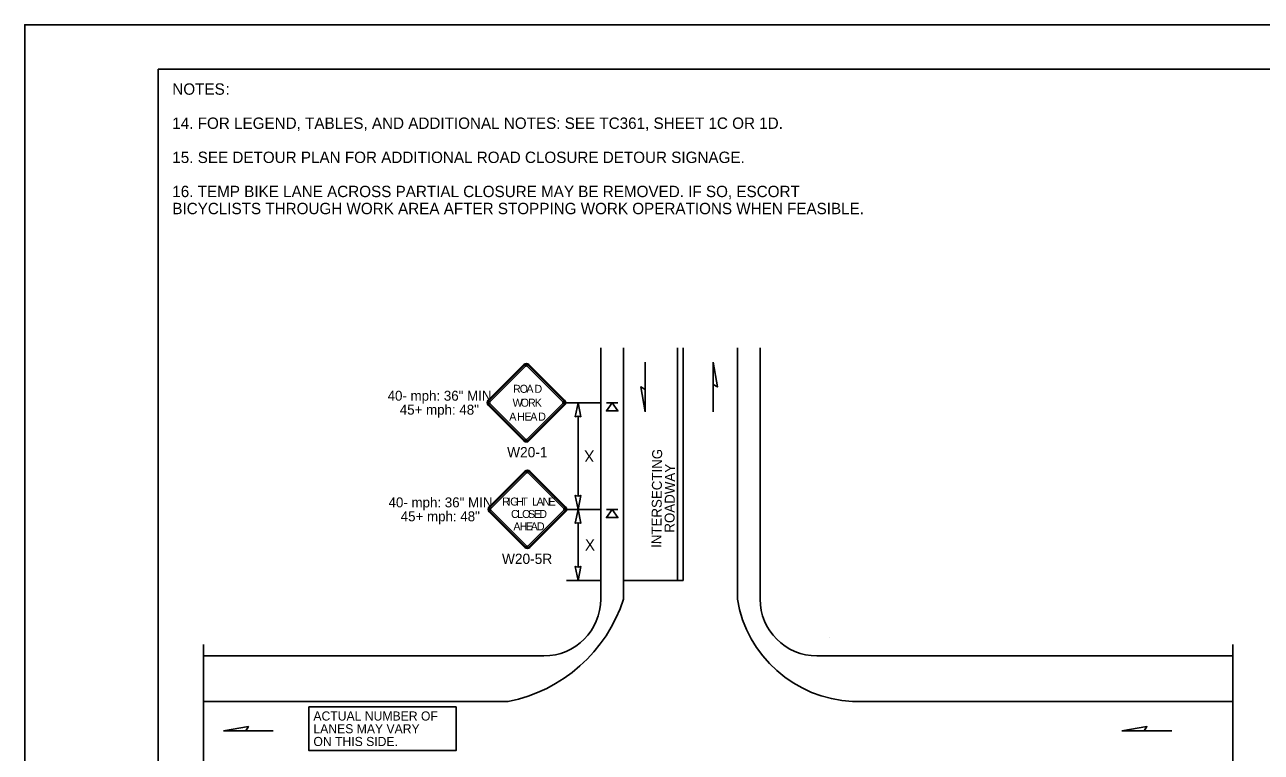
# Model space of a CAD drawing. Extents: x 99958 to 100176, y 99935 to 100011.
# Drawn here: x 100039.06 to 100047.76, y 99975.57 to 99980.69 of the extents above; entities that cross this region are included whole.
import ezdxf

# ---------------------------------------------------------------- set-up
doc = ezdxf.new("R2010")
doc.units = 0
for name, color, linetype in [('RD_ED_ShoulderPavedEdge', 7, 'Continuous'), ('RD_MK_LineDblYellowCenter', 7, 'Continuous'), ('RD_MK_LineEdgeWhite', 7, 'Continuous'), ('RD_MK_LineStop', 7, 'Continuous'), ('SH_DE_DetailBody1Text', 7, 'Continuous'), ('SH_GI_GeneralNotesBodyText', 7, 'Continuous'), ('SH_GI_PlotLimits', 7, 'Continuous'), ('SH_GI_SheetBorder', 7, 'Continuous'), ('SH_TI_Tables', 7, 'Continuous'), ('TR_SN_ConstructionSigns', 7, 'Continuous'), ('TR_WZ_PortableSignMountBlk-Org', 7, 'Continuous'), ('TR_WZ_WorkZoneDetails', 7, 'Continuous'), ('TR_WZ_WorkZoneTextCurrent', 7, 'Continuous')]:
    doc.layers.add(name, color=color, linetype=linetype)

msp = doc.modelspace()

# ---------------------------------------------------------------- linework, layer by layer
at = {"layer": 'RD_ED_ShoulderPavedEdge'}
for p, q in [((100042.7119, 99976.2485), (100040.32, 99976.2485)), ((100047.555, 99976.2485), (100044.6319, 99976.2485))]:
    msp.add_line(p, q, dxfattribs=at)
for points in [[(100043.1119, 99978.415), (100043.1119, 99976.6485)], [(100044.2319, 99978.415), (100044.2319, 99976.6485)]]:
    msp.add_lwpolyline(points, dxfattribs=at)
for centre, start, end in [((100042.7119, 99976.6485), 270, 0), ((100044.6319, 99976.6485), 180, 270)]:
    msp.add_arc(centre, 0.4, start, end, dxfattribs=at)
at = {"layer": 'RD_MK_LineDblYellowCenter'}
for p, q in [((100043.6519, 99978.415), (100043.6519, 99976.7785)), ((100043.6919, 99978.415), (100043.6919, 99976.7785))]:
    msp.add_line(p, q, dxfattribs=at)
at = {"layer": 'RD_MK_LineEdgeWhite'}
for p, q in [((100043.2719, 99976.6485), (100043.2719, 99978.415)), ((100044.0719, 99976.6485), (100044.0719, 99978.415)), ((100042.4619, 99975.9285), (100040.32, 99975.9285)), ((100047.555, 99975.9285), (100044.8819, 99975.9285))]:
    msp.add_line(p, q, dxfattribs=at)
for centre, radius, start, end in [((100042.257, 99976.9747), 1.0661, 281.08423, 342.18285), ((100044.9219, 99976.789), 0.8615, 189.3884, 267.34452)]:
    msp.add_arc(centre, radius, start, end, dxfattribs=at)
at = {"layer": 'RD_MK_LineStop'}
msp.add_line((100043.6919, 99976.7785), (100043.2719, 99976.7785), dxfattribs=at)
at = {"layer": 'SH_GI_PlotLimits'}
msp.add_lwpolyline([(100039.0625, 99969.6875), (100056.0625, 99969.6875), (100056.0625, 99980.6875), (100039.0625, 99980.6875)], close=True, dxfattribs=at)
at = {"layer": 'SH_GI_SheetBorder'}
for q in [(100040, 99970), (100055.75, 99980.375)]:
    msp.add_line((100040, 99980.375), q, dxfattribs=at)
at = {"layer": 'SH_TI_Tables'}
msp.add_lwpolyline([(100041.0598, 99975.8901), (100042.0943, 99975.8901), (100042.0943, 99975.5831), (100041.0598, 99975.5831)], close=True, dxfattribs=at)
at = {"layer": 'TR_SN_ConstructionSigns'}
for p, q in [((100042.5715, 99978.2978), (100042.3209, 99978.0472)), ((100042.5765, 99978.2928), (100042.3259, 99978.0422)), ((100042.3328, 99978.0353), (100042.5834, 99978.2858)), ((100042.5953, 99978.2858), (100042.8459, 99978.0353)), ((100042.8529, 99978.0422), (100042.6023, 99978.2928)), ((100042.8579, 99978.0472), (100042.6073, 99978.2978)), ((100042.3209, 99978.0114), (100042.5715, 99977.7608)), ((100042.3259, 99978.0164), (100042.5765, 99977.7658)), ((100042.5834, 99977.7728), (100042.3328, 99978.0233)), ((100042.8459, 99978.0233), (100042.5953, 99977.7728)), ((100042.6023, 99977.7658), (100042.8529, 99978.0164)), ((100042.6073, 99977.7608), (100042.8579, 99978.0114)), ((100042.5782, 99977.5478), (100042.3276, 99977.2972)), ((100042.5831, 99977.5428), (100042.3325, 99977.2922)), ((100042.3395, 99977.2853), (100042.5901, 99977.5358)), ((100042.602, 99977.5358), (100042.8526, 99977.2853)), ((100042.8596, 99977.2922), (100042.609, 99977.5428)), ((100042.8645, 99977.2972), (100042.6139, 99977.5478)), ((100042.3276, 99977.2614), (100042.5782, 99977.0108)), ((100042.3325, 99977.2664), (100042.5831, 99977.0158)), ((100042.5901, 99977.0228), (100042.3395, 99977.2733)), ((100042.8526, 99977.2733), (100042.602, 99977.0228)), ((100042.609, 99977.0158), (100042.8596, 99977.2664)), ((100042.6139, 99977.0108), (100042.8645, 99977.2614))]:
    msp.add_line(p, q, dxfattribs=at)
for centre, radius, start, end in [((100042.5894, 99978.2799), 0.0253, 45, 135), ((100042.5894, 99978.2799), 0.0183, 45, 135), ((100042.5894, 99978.2799), 0.00844, 45, 135), ((100042.3388, 99978.0293), 0.0253, 135, 225.00001), ((100042.3388, 99978.0293), 0.0183, 135, 225.00001), ((100042.3388, 99978.0293), 0.00844, 135, 225.00001), ((100042.84, 99978.0293), 0.00844, 315.00002, 45), ((100042.84, 99978.0293), 0.0183, 315.00002, 45), ((100042.84, 99978.0293), 0.0253, 315.00001, 45.00001), ((100042.5894, 99977.7787), 0.0253, 225.00001, 315.00001), ((100042.5894, 99977.7787), 0.0183, 225.00001, 315.00002), ((100042.5894, 99977.7787), 0.00844, 225.00001, 315.00002), ((100042.596, 99977.5299), 0.0253, 45, 135), ((100042.596, 99977.5299), 0.0183, 45, 135), ((100042.596, 99977.5299), 0.00844, 45, 135), ((100042.3455, 99977.2793), 0.0253, 135, 225.00001), ((100042.3455, 99977.2793), 0.0183, 135, 225.00001), ((100042.3455, 99977.2793), 0.00844, 135, 225.00001), ((100042.8466, 99977.2793), 0.00844, 315.00002, 45), ((100042.8466, 99977.2793), 0.0183, 315.00002, 45), ((100042.8466, 99977.2793), 0.0253, 315.00001, 45.00001), ((100042.596, 99977.0287), 0.0253, 225.00001, 315.00001), ((100042.596, 99977.0287), 0.0183, 225.00001, 315.00002), ((100042.596, 99977.0287), 0.00844, 225.00001, 315.00002)]:
    msp.add_arc(centre, radius, start, end, dxfattribs=at)
at = {"layer": 'TR_WZ_PortableSignMountBlk-Org'}
for p, q in [((100043.1519, 99978.0293), (100043.2319, 99978.0293)), ((100043.1519, 99977.2793), (100043.2319, 99977.2793))]:
    msp.add_line(p, q, dxfattribs=at)
for points in [[(100043.1919, 99978.0293), (100043.2319, 99977.9718), (100043.1519, 99977.9718)], [(100043.1919, 99977.2793), (100043.2319, 99977.2218), (100043.1519, 99977.2218)]]:
    msp.add_lwpolyline(points, close=True, dxfattribs=at)
at = {"layer": 'TR_WZ_WorkZoneDetails'}
for p, q in [((100043.4242, 99978.1221), (100043.4242, 99978.315)), ((100043.9015, 99978.1578), (100043.9015, 99977.9649)), ((100043.1119, 99978.0293), (100042.8653, 99978.0293)), ((100042.9519, 99977.9356), (100042.9519, 99977.373)), ((100043.1119, 99977.2793), (100042.8719, 99977.2793)), ((100042.9519, 99977.1856), (100042.9519, 99976.873)), ((100043.1119, 99976.7793), (100042.8719, 99976.7793)), ((100044.7227, 99976.3806), (100044.7227, 99976.3806)), ((100040.6169, 99975.721), (100040.8098, 99975.721)), ((100046.9327, 99975.721), (100047.1256, 99975.721))]:
    msp.add_line(p, q, dxfattribs=at)
for points in [[(100043.9015, 99978.315), (100043.9323, 99978.1399), (100043.9015, 99978.1578)], [(100043.4242, 99977.9649), (100043.3933, 99978.1399), (100043.4242, 99978.1221)], [(100042.9519, 99978.0293), (100042.9712, 99977.931), (100042.9519, 99977.9356), (100042.9327, 99977.931)], [(100042.9519, 99977.2793), (100042.9712, 99977.3776), (100042.9519, 99977.373), (100042.9327, 99977.3776)], [(100042.9519, 99977.2793), (100042.9712, 99977.181), (100042.9519, 99977.1856), (100042.9327, 99977.181)], [(100042.9519, 99976.7793), (100042.9712, 99976.8776), (100042.9519, 99976.873), (100042.9327, 99976.8776)], [(100040.4597, 99975.721), (100040.6347, 99975.7519), (100040.6169, 99975.721)], [(100046.7755, 99975.721), (100046.9506, 99975.7519), (100046.9327, 99975.721)]]:
    msp.add_lwpolyline(points, close=True, dxfattribs=at)
for points in [[(100040.32, 99973.9925), (100040.32, 99975.083), (100040.24, 99975.083), (100040.4, 99975.2379), (100040.32, 99975.2379), (100040.32, 99976.3285)], [(100047.555, 99973.9925), (100047.555, 99975.083), (100047.475, 99975.083), (100047.635, 99975.2379), (100047.555, 99975.2379), (100047.555, 99976.3285)]]:
    msp.add_lwpolyline(points, dxfattribs=at)

# ---------------------------------------------------------------- texts
at = {"layer": 'SH_DE_DetailBody1Text'}
for s, p in [('INTERSECTING', (100043.5379, 99977.0077)), ('ROADWAY', (100043.6299, 99977.1152))]:
    msp.add_text(s, height=0.07, rotation=89.5374, dxfattribs=at).set_placement(p)
at = {"layer": 'SH_GI_GeneralNotesBodyText'}
for s, p in [('NOTES', (100040.1, 99980.195)), (':', (100040.4743, 99980.195)), ('14. FOR LEGEND, TABLES, AND ADDITIONAL NOTES: SEE TC361, SHEET 1C OR 1D.', (100040.1, 99979.955)), ('15. SEE DETOUR PLAN FOR ADDITIONAL ROAD CLOSURE DETOUR SIGNAGE.', (100040.1, 99979.715)), ('16. TEMP BIKE LANE ACROSS PARTIAL CLOSURE MAY BE REMOVED. IF SO, ESCORT ', (100040.1, 99979.475)), ('BICYCLISTS THROUGH WORK AREA AFTER STOPPING WORK OPERATIONS WHEN FEASIBLE.', (100040.1, 99979.355))]:
    msp.add_text(s, height=0.08, rotation=360, dxfattribs=at).set_placement(p)
at = {"layer": 'SH_TI_Tables'}
for s, p in [('ACTUAL NUMBER OF', (100041.0918, 99975.7941)), ('LANES MAY VARY', (100041.0918, 99975.7045)), ('ON THIS SIDE.', (100041.0918, 99975.6149))]:
    msp.add_text(s, height=0.064, rotation=360, dxfattribs=at).set_placement(p)
at = {"layer": 'TR_SN_ConstructionSigns'}
for s, p in [('R', (100042.4948, 99978.0988)), ('O', (100042.5417, 99978.0988)), ('A', (100042.5892, 99978.0988)), ('D', (100042.6457, 99978.0988)), ('W', (100042.4919, 99978.0012)), ('O', (100042.5488, 99978.0012)), ('R', (100042.6003, 99978.0012)), ('K', (100042.6475, 99978.0012)), ('A', (100042.4684, 99977.9035)), ('H', (100042.5247, 99977.9035)), ('E', (100042.5764, 99977.9035)), ('A', (100042.6158, 99977.9035)), ('D', (100042.6721, 99977.9035)), ('R', (100042.4189, 99977.306)), ('I', (100042.4582, 99977.306)), ('G', (100042.4753, 99977.306)), ('H', (100042.5161, 99977.306)), ('T', (100042.554, 99977.306)), ('L', (100042.629, 99977.306)), ('A', (100042.6604, 99977.306)), ('N', (100042.7029, 99977.306)), ('E', (100042.7445, 99977.306)), ('C', (100042.4807, 99977.2188)), ('L', (100042.5235, 99977.2188)), ('O', (100042.5589, 99977.2188)), ('S', (100042.6005, 99977.2188)), ('E', (100042.6416, 99977.2188)), ('D', (100042.6799, 99977.2188)), ('A', (100042.4976, 99977.1316)), ('H', (100042.5415, 99977.1316)), ('E', (100042.5854, 99977.1316)), ('A', (100042.6191, 99977.1316)), ('D', (100042.663, 99977.1316))]:
    msp.add_text(s, height=0.0562, dxfattribs=at).set_placement(p)
for s, p in [('W20-1', (100042.4536, 99977.6454)), ('W20-5R', (100042.4174, 99976.8954))]:
    msp.add_text(s, height=0.072, rotation=360, dxfattribs=at).set_placement(p)
at = {"layer": 'TR_WZ_WorkZoneDetails'}
for s, p in [('40- mph: 36" MIN', (100041.6134, 99978.0433)), ('45+ mph: 48"', (100041.699, 99977.9453)), ('40- mph: 36" MIN', (100041.62, 99977.2933)), ('45+ mph: 48"', (100041.7056, 99977.1953))]:
    msp.add_text(s, height=0.07, dxfattribs=at).set_placement(p)
at = {"layer": 'TR_WZ_WorkZoneTextCurrent'}
msp.add_text('X', height=0.08, rotation=180, dxfattribs=at).set_placement((100043.0667, 99977.6943))
msp.add_text('X', height=0.08, dxfattribs=at).set_placement((100043.0002, 99976.9893))

doc.saveas('drawing.dxf')
